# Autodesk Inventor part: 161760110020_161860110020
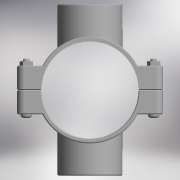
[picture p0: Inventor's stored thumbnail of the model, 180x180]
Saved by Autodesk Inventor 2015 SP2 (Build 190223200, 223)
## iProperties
Created: 2017-05
Part Number: 161760110020_161860110020
Material: Generic
Description: PLASSON DOUBLE SADDLE 110-2"
Document SubType Name: Modeling
Designer: KIM
Density: 1 g/cm^3
Appearance: Default
Author: KIM
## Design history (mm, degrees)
derived "16176.ipt"
feature "Solid1::16176.ipt"
feature "Solid2::16176.ipt"
tag "TaggingFeature1"
body "Solid1"
body "Solid2"
other parameters: "d0" = 121, "d1" = 165, "d2" = 55, "d4" = 116, "d5" = 0, "d6" = 8.25, "d7" = 165, "d8" = 0.1, "d10" = 0, "d11" = 1.1, "d20" = 1.1, "d23" = 1.1, "d36" = 13, "d37" = 10.4, "d38" = 63, "d39" = 0, "d40" = 3, "d41" = 5, "d42" = 0, "d43" = 8, "d44" = 3, "d45" = 0, "d46" = 1.1, "d52" = 56.656, "d54" = 0, "d57" = 0, "d58" = 118.8, "d60" = 0, "d62" = 13, "d63" = 10.4, "d66" = 95.2, "d67" = 194, "d68" = 73.6528, "d69" = 56.656, "d71" = 0, "d74" = 0, "d75" = 1.1, "G_" = 56.656, "A_" = 97, "L_" = 165, "L_1" = 116
